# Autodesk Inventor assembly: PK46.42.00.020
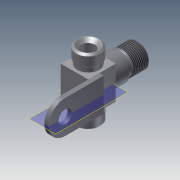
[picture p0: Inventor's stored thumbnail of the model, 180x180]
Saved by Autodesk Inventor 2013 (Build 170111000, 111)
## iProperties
Created: 2005-06
Part Number: PK46.42.00.020
Document SubType Name: Assembly
Designer: salex
Manufacturer: Standard
Standards Organization: Custom
Author: salex
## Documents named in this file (4)
- D:\FrontLoaderVault\Data\Assy, Chassis, Front\PK46.42.00.020.iam
- D:\FrontLoaderVault\Data\Assy, Chassis, Front\PK46.42.00.021.ipt
- D:\FrontLoaderVault\Data\Assy, Chassis, Front\PK46.42.00.022.ipt
- D:\FrontLoaderVault\Data\Assy, Chassis, Front\027.03.01.012.ipt
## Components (3 placed, 3 different names)
1. PK46.42.00.021:1 — Insert:1, Flush:1, Mate:2, Mate:3
2. PK46.42.00.022:1 — Flush:1, Mate:2, Mate:3
3. 027.03.01.012:1 — Insert:1
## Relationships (4: Mate 2, Insert 1, Flush 1)
- Insert:1: PK46.42.00.021:1 ↔ 027.03.01.012:1
- Flush:1: PK46.42.00.021:1 ↔ PK46.42.00.022:1
- Mate:2: PK46.42.00.021:1 ↔ PK46.42.00.022:1
- Mate:3: PK46.42.00.021:1 ↔ PK46.42.00.022:1
